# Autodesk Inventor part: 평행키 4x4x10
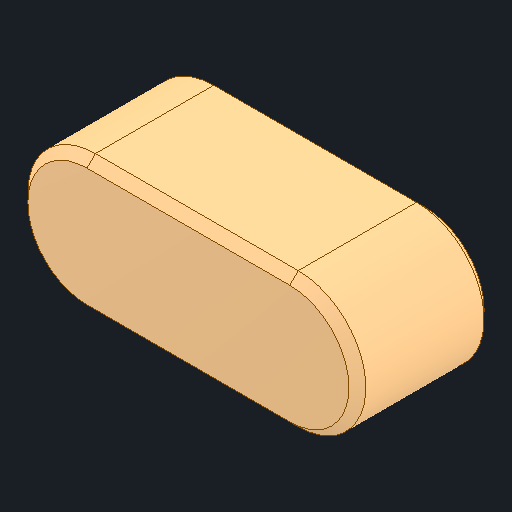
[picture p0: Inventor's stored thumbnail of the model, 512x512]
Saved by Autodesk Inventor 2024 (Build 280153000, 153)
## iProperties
Created: 2025-02
Part Number: 평행키 4x4x10
Material: 강철, 연강
Description: 키 및 해당 키홈
Document SubType Name: Modeling
Designer: kh_501
Density: 7.85 g/cm^3
Appearance: 기본값
Author: jhkim
Sending System: Autodesk Inventor 2025
Preprocessor: ST-DEVELOPER v20
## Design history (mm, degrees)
node "평행키 4x4x101"
node "솔리드1"
body "Solid1"
